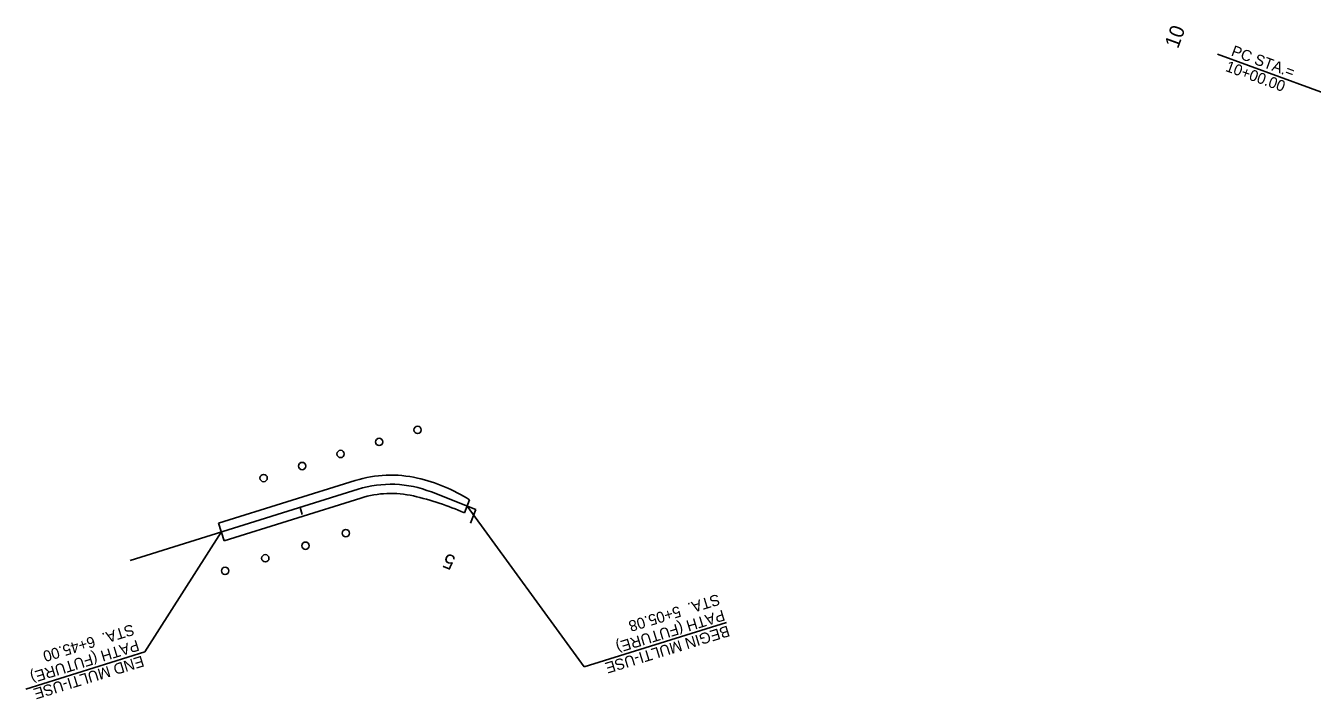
# Model space of a CAD drawing. Extents: x 1968740 to 1970715, y 796044 to 797557.
# Drawn here: x 1968740 to 1969442, y 797178 to 797545 of the extents above; entities that cross this region are included whole.
import ezdxf

# ---------------------------------------------------------------- set-up
doc = ezdxf.new("R2010")
doc.units = 0
for name, color, linetype in [('BR_CONCRETE', 7, 'Continuous'), ('RD_HC_CL_Rel', 7, 'Continuous'), ('RD_HC_Data_Rel', 7, 'Continuous'), ('RD_HC_Data_Tic_Rel', 7, 'Continuous'), ('RD_HC_TX_Rel_Sta50', 7, 'Continuous'), ('RD_PD_Final_TrvlWay', 7, 'Continuous'), ('RD_PD_Final_TX', 7, 'Continuous')]:
    doc.layers.add(name, color=color, linetype=linetype)

msp = doc.modelspace()

# ---------------------------------------------------------------- linework, layer by layer
at = {"layer": 'BR_CONCRETE'}
for centre in [(1968954.04, 797324.87), (1968933.04, 797318.3), (1968912.04, 797311.73), (1968891.05, 797305.16), (1968870.05, 797298.59), (1968914.87, 797268.55), (1968892.92, 797261.68), (1968870.97, 797254.81), (1968849.02, 797247.95)]:
    msp.add_circle(centre, 2, dxfattribs=at)
at = {"layer": 'RD_HC_CL_Rel'}
for p, q in [((1968921.55, 797292.47), (1968797.26, 797253.58)), ((1968985.77, 797281.41), (1968961.56, 797291))]:
    msp.add_line(p, q, dxfattribs=at)
msp.add_arc((1968939.47, 797235.21), 60, 68.39999, 107.37718, dxfattribs=at)
at = {"layer": 'RD_HC_Data_Rel'}
msp.add_line((1969390.42, 797529.95), (1969472, 797500.15), dxfattribs=at)
at = {"layer": 'RD_HC_Data_Tic_Rel'}
for p, q in [((1968889.93, 797282.58), (1968891.12, 797278.76)), ((1968985.77, 797281.41), (1968982.83, 797273.97))]:
    msp.add_line(p, q, dxfattribs=at)
at = {"layer": 'RD_PD_Final_TrvlWay'}
for p, q in [((1968920.05, 797297.24), (1968845.46, 797273.9)), ((1968923.04, 797287.7), (1968848.44, 797264.36)), ((1968982.42, 797286.76), (1968979.58, 797279.56)), ((1968848.44, 797264.36), (1968845.46, 797273.9))]:
    msp.add_line(p, q, dxfattribs=at)
for centre, radius, start, end in [((1968939.47, 797235.21), 65, 77.08135, 107.37718), ((1968933.46, 797209), 91.89, 57.79824, 77.08135), ((1968939.47, 797235.21), 55, 77.08135, 107.37718), ((1968917.54, 797139.6), 153.1, 66.09479, 77.08135)]:
    msp.add_arc(centre, radius, start, end, dxfattribs=at)
at = {"layer": 'RD_PD_Final_TX'}
for p, q in [((1968981.05, 797283.28), (1969044.97, 797195.56)), ((1968846.95, 797269.13), (1968805.28, 797203.75)), ((1969044.97, 797195.56), (1969122.55, 797219.84)), ((1968740.26, 797183.4), (1968805.28, 797203.75))]:
    msp.add_line(p, q, dxfattribs=at)

# ---------------------------------------------------------------- texts
at = {"layer": 'RD_HC_Data_Rel'}
for s, height, rotation, p in [('10', 8, 69.92961, (1969368.87, 797532.6)), ('PC STA.=', 6, 339.92961, (1969397.45, 797529.29)), ('10+00.00', 6, 339.92961, (1969394.36, 797520.84))]:
    msp.add_text(s, height=height, rotation=rotation, dxfattribs=at).set_placement(p)
at = {"layer": 'RD_HC_TX_Rel_Sta50'}
msp.add_text('5', height=8, rotation=158.39999, dxfattribs=at).set_placement((1968975.35, 797255.59))
at = {"layer": 'RD_PD_Final_TX'}
for s, p in [('STA.  5+05.08', (1969117.87, 797235.41)), ('PATH (FUTURE)', (1969120.51, 797226.81)), ('STA.  6+45.00', (1968798.37, 797218.95)), ('BEGIN MULTI-USE', (1969123.15, 797218.2)), ('PATH (FUTURE)', (1968801.01, 797210.34)), ('END MULTI-USE', (1968803.65, 797201.74))]:
    msp.add_text(s, height=5.9996, rotation=197.04529, dxfattribs=at).set_placement(p)

doc.saveas('drawing.dxf')
